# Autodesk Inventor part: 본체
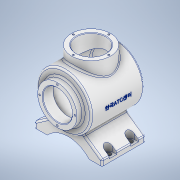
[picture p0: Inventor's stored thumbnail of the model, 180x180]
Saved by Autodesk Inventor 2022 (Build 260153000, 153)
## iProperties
Created: 2023-04
Part Number: 본체
Material: 알루미늄 6061
Document SubType Name: Modeling
Designer: Admin
Mass: 1296.69 g
Surface Area: 1060.45 cm^2
Volume: 480.256 cm^3
Density: 2.7 g/cm^3
Appearance: 알루미늄 - 평지
Author: Admin
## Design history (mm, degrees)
sketch "스케치1"
  geometry: L1 (0, -87.453)-(0, 84.575) reference; L2 (-10.134, 0)-(60.805, 0) reference; L3 (0, 60)-(36, 60); L4 (36, 60)-(36, 48); L5 (36, 48)-(50, 48); L6 (50, 48)-(50, -48.336); L7 (36, -60)-(0, -60); L8 (0, -60)-(0, 60); A1 r 113 centre (0, 53) between (0, -60) and (50, -48.336)
  constraints: 12 end point, 4 perpendicular, 4 point on line, 2 point on circle, 1 centre point, 1 collinear, 1 horizontal, 1 tangent, 1 other
  dimensions: "d4" = 120 distance between parallel lines of L7 L3; "d5" = 50 distance between parallel lines of L8 L6; "d6" = 36 distance between parallel lines of L8 L4; "d7" = 108 distance between parallel lines of L7 L5; "d8" = 226 diameter of A1
revolve "회전1" sketch "스케치1" stored, may be unused: angle "d9" = 90 deg
sketch "스케치2"
  geometry: L1 (-62, -77)-(62, -77); L2 (62, -77)-(62, -67); L3 (62, -67)-(17.576, -35.894); L4 (17.576, -35.894)-(-17.576, -35.894); L5 (-17.576, -35.894)-(-62, -67); L6 (-62, -67)-(-62, -77); L7 (0, -116.207)-(0, 77.701) reference; L8 (-111.694, 0)-(114.644, 0) reference; L9 (-25.806, -60)-(31.051, -60); A1 r 52.096 centre (0, -112.096) between (38.5, -77) and (-38.5, -77); 1 further point
  constraints: 14 end point, 2 horizontal, 2 parallel, 2 point on circle, 2 point on line, 1 centre point, 1 perpendicular, 1 symmetric about line, 1 tangent, 1 other
  dimensions: "d10" = 124 distance of L1.start L1.end; "d11" = 10 distance of L1.end L2.end; "d12" = 10 distance of L5.end L1.start; "d13" = 55 deg angle of L2 L3; "d14" = 55 deg angle of L6 L5; "d15" = 17 distance between parallel lines of L1 L9; "d16" = 77 distance between parallel lines of L8 L1; "d17" = 35.152 distance of L3.end L4.end; "d19" = 77 distance of A1.start A1.end
extrude "돌출1" join sketch "스케치2" stored distance "d20" = 80; taper "d21" = 0 deg
node "작업 평면1"
sketch "스케치4"
  geometry: L1 (-36, 60)-(36, 60) reference; C1 r 36 at (0, -2); 1 further point
  constraints: 1 centre point, 1 vertical alignment
  dimensions: "d29" = 72 diameter of C1; "d30" = 62 distance from line of L1 C1.centre
extrude "돌출2" join sketch "스케치4" distance "d31" = 30; taper "d32" = 0 deg
sketch "스케치3"
  geometry: L1 (-50, -48.336)-(50, -48.336) reference; L2 (-42.278, -40)-(-42.278, -40) reference; L3 (-42.278, -40)-(-42.278, 40) reference; L4 (-42.278, 40)-(-42.278, 40) reference; L5 (-42.278, 40)-(-42.278, -40) reference; L6 (-50, 48)-(50, 48) reference; L7 (-50, -48.336)-(50, -48.336) reference; L8 (-36, 60)-(36, 60) reference; L9 (-36, 48)-(36, 48) reference; L10 (-60, 40)-(-60, -40) reference; L11 (-77, -40)-(-77, 40) reference; L12 (-36, 60)-(36, 60) reference; L13 (0, 60)-(27, 60); L14 (27, 41)-(43, 41); L15 (43, 41)-(43, -43.887); L16 (27, 60)-(27, 41); L17 (0, 60)-(0, -53); A1 r 113 centre (0, 53) between (-50, -48.336) and (50, -48.336) reference; A2 r 106 centre (0, 53) between (0, -53) and (43, -43.887); 1 further point
  constraints: 10 end point, 2 perpendicular, 2 point on circle, 1 centre point, 1 horizontal, 1 midpoint, 1 parallel, 1 point on line
  dimensions: "d23" = 7 radial gap between concentric circles of A2 A1; "d24" = 27 distance of L13.start L13.end; "d25" = 43 distance between parallel lines of L17 L15; "d26" = 19 distance between parallel lines of L8 L14
revolve "회전2" sketch "스케치3" stored, may be unused: angle "d27" = 90 deg
sketch "스케치5"
  geometry: C1 r 36 at (0, 0) reference; C2 r 27 at (0, 0); 1 further point
  constraints: 1 centre point, 1 coincident
  dimensions: "d33" = 54 diameter of C2
extrude "돌출3" cut sketch "스케치5" distance "d34" = 40; taper "d35" = 0 deg
sketch "스케치6" dims "d36" = 65
  geometry: C1 r 27 at (0, 0) reference; C2 r 36 at (0, 0) reference; 3 further points
  constraints: 2 horizontal alignment, 1 coincident, 2 other
hole "구멍1" sketch "스케치6" at (-32.5, 0) diameter "d37" = 3.242; stored, may be unused: countersink angle "d41" = 90 deg, drill point angle "d43" = 118 deg; dims "d38" = 8, "d39" = 4, "d40" = 2, "d42" = 10
sketch "스케치7" dims "d47" = 65
  geometry: 3 further points
  constraints: 2 vertical alignment, 1 coincident, 2 other
hole "구멍2" sketch "스케치7" at (0, 32.5) diameter "d48" = 3.242; stored, may be unused: countersink angle "d52" = 90 deg, drill point angle "d54" = 118 deg; dims "d49" = 8, "d50" = 4, "d51" = 2, "d53" = 10
sketch "스케치8"
  geometry: L1 (23.5, -80)-(23.5, 0) reference; L2 (0, 0)-(23.5, 0) reference; L3 (0, -80)-(0, 0) reference; L4 (23.5, -80)-(0, -80) reference; L5 (-77, -80)-(-77, 0) reference; L6 (-100.5, 0)-(-77, 0) reference; L7 (-100.5, 0)-(-100.5, -80) reference; L8 (-77, -80)-(-100.5, -80) reference; C1 r 4.5 at (-92.5, -20); C2 r 4.5 at (-92.5, -60); C3 r 4.5 at (15.5, -60); C4 r 4.5 at (15.5, -20); 1 further point
  constraints: 4 centre point, 2 horizontal alignment, 2 vertical alignment
  dimensions: "d58" = 9 diameter of C4; "d59" = 9 diameter of C3; "d60" = 9 diameter of C2; "d61" = 9 diameter of C1; "d62" = 40 distance of C4.centre C3.centre; "d63" = 20 distance from line of L2 C4.centre; "d64" = 108 distance of C1.centre C4.centre; "d65" = 8 distance from line of L1 C4.centre
extrude "돌출4" cut sketch "스케치8" distance "d66" = 6; taper "d67" = 0 deg
sketch "스케치9"
  geometry: L1 (0, 7)-(-8, 7); L2 (-8, -60)-(-8, 20) reference; L3 (-8, 7)-(-8, -7); L4 (-8, -7)-(0, -7); L5 (0, -33)-(-8, -33); L6 (0, -47)-(-8, -47); L7 (-8, -47)-(-8, -33); L8 (108, 7)-(116, 7); L9 (116, -60)-(116, 20) reference; L10 (108, -7)-(116, -7); L11 (108, -33)-(116, -33); L12 (108, -47)-(116, -47); L13 (116, 7)-(116, -7); L14 (116, -33)-(116, -47); C1 r 4.5 at (0, 0) reference; C2 r 4.5 at (0, -40) reference; C3 r 4.5 at (108, -40) reference; C4 r 4.5 at (108, 0) reference; A1 r 7 centre (0, 0) between (0, -7) and (0, 7); A2 r 7 centre (0, -40) between (0, -47) and (0, -33); A3 r 7 centre (108, -40) between (108, -33) and (108, -47); A4 r 7 centre (108, 0) between (108, 7) and (108, -7); 1 further point
  constraints: 24 end point, 8 point on circle, 8 tangent, 7 point on line, 4 centre point, 4 coincident, 4 equal length, 4 perpendicular, 2 horizontal, 1 vertical
  dimensions: "d68" = 14 diameter of A4; "d69" = 14 diameter of A3 (= d68); "d70" = 14 diameter of A2; "d71" = 14 diameter of A1 (= d70); "d72" = 8 distance of L3.end L4.end
extrude "돌출5" cut sketch "스케치9" distance "d73" = 20; taper "d74" = 0 deg
sketch "스케치10"
  geometry: L1 (-27, 60)-(27, 60) reference; 2 further points
  constraints: 1 vertical alignment, 1 other
  dimensions: "d75" = 62 distance from line of L1 point (0, -2)
feature "엠보싱1" sketch "스케치10" dims "d76" = 0.5, "d77" = 0
fillet "모깎기1" dims "d78" = 3
fillet "모깎기2" dims "d79" = 3
chamfer "모따기1" distance "d80" = 1; stored, may be unused: second distance "d81" = 2, angle "d82" = 45 deg
fillet "모깎기3" dims "d83" = 3
fillet "모깎기4" dims "d84" = 3
node "솔리드1"
pattern_circular "원형 패턴1" dims angle "d45" = 360 deg
pattern_circular "원형 패턴2" dims angle "d56" = 360 deg
node "투영된 루프1"
node "투영된 루프2"
node "투영된 루프3"
node "투영된 루프4"
node "투영된 루프5"
node "투영된 루프6"
node "투영된 루프7"
node "투영된 루프8"
node "투영된 루프9"
node "투영된 루프10"
node "투영된 루프11"
feature "A9D066F2-1C7D-4E18-AEED-F7BC21143FA4" dims "d37" = 3.242, "d38" = 8, "d39" = 4, "d40" = 2, "d41" = 90 deg, "d42" = 10, "d43" = 118 deg
other parameters: "d22" = 7, "d28" = 65
